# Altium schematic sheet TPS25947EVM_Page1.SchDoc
size 431 x 279 mm; Date: Not shown in title block; ApprovedBy: Not shown in title block; CheckedBy: Not shown in title block; Author: Not shown in title block; CompanyName: Not shown in title block; Engineer: Not shown in title block; Organization: Not shown in title block; Address1: Not shown in title block; Address2: Not shown in title block; Address3: Not shown in title block; Address4: Not shown in title block; DocumentNumber: 1; Revision: Use project parameter SCH_Rev; SheetNumber: 1; SheetTotal: 3; PageSetup: Record=PageOptions¦CenterHorizontal=True¦CenterVertical=True¦PrintScale=1.00¦XCorrection=1.00¦YCorrection=1.00¦PrintKind=0¦BorderSize=5000000¦LeftOffset=0¦BottomOffset=0¦Orientation=2¦PaperLength=1000¦PaperWidth=1000¦Scale=100¦PaperSource=15¦PrintQuality=600¦MediaType=1¦DitherType=10¦PaperKind=Letter¦PrintScaleMode=1
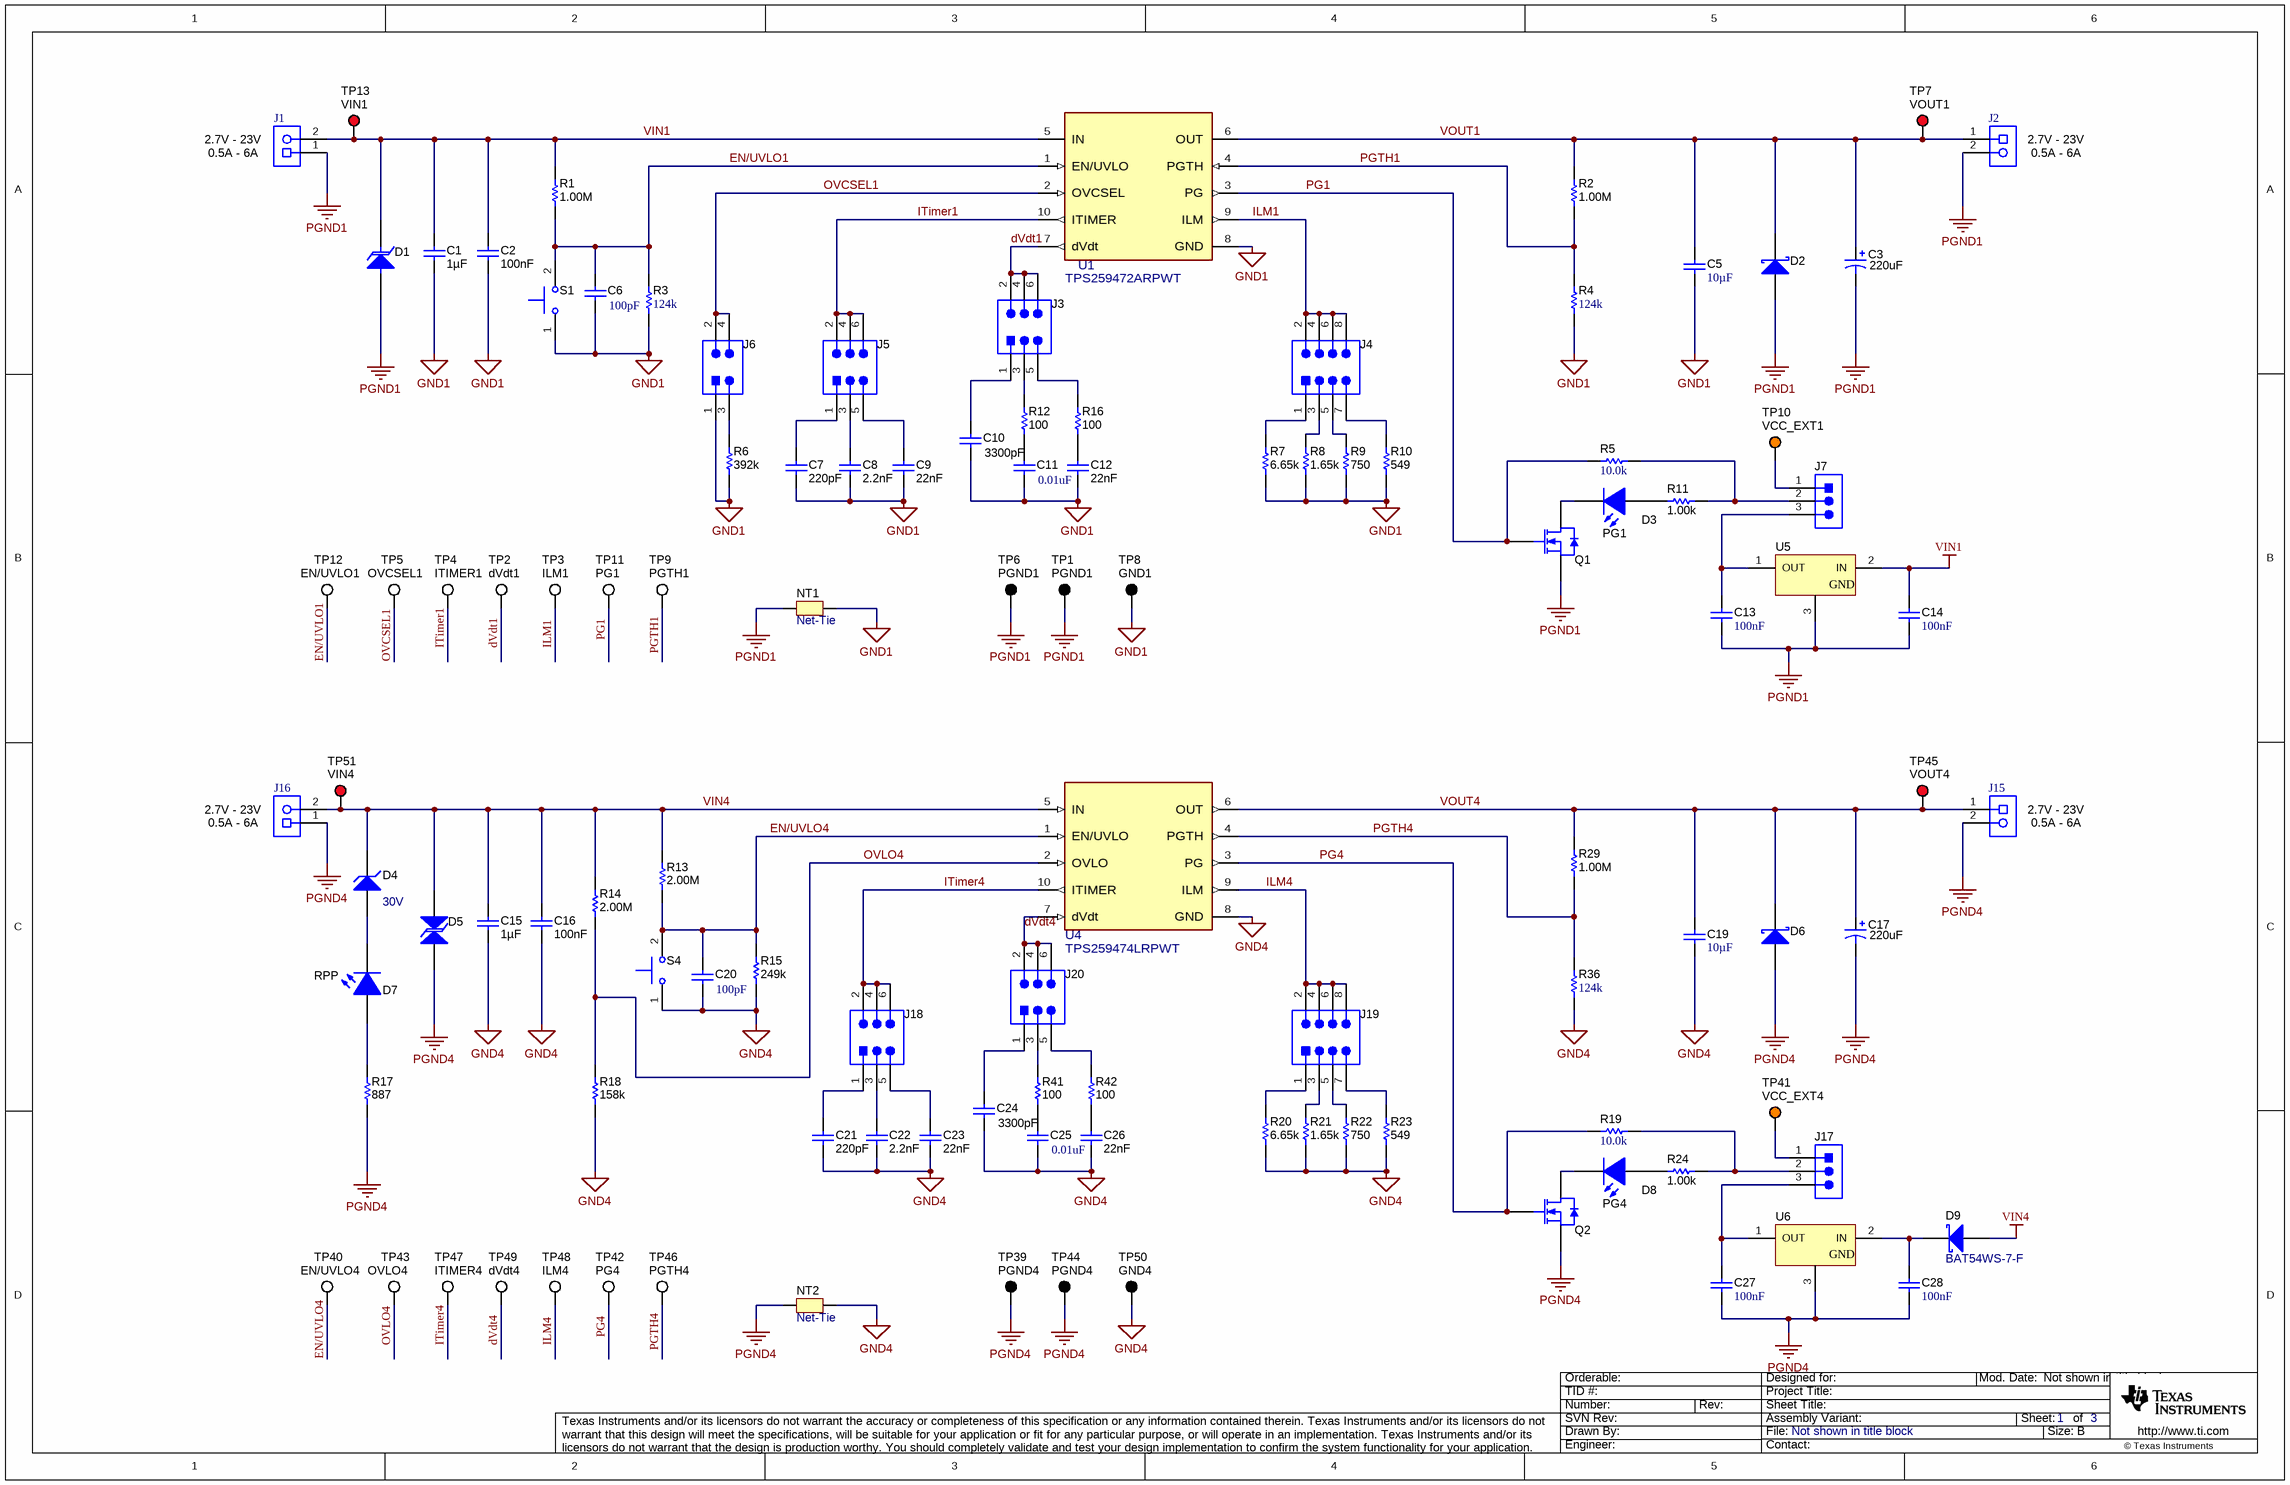
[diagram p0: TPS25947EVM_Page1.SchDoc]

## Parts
C1  Cap_F: 1µF  [0603]  (hidden comment: C1608X7R1V105K080AC)
C2  Cap_F: 100nF  [0603]  (hidden comment: C1608X7R1H104K080AA)
C3  ValueDisplayed: 220uF  [SM_RADIAL_G]  (hidden comment: EEE-FC1V221P)
C5  ValueDisplayed: 10µF  [1206_190]  (hidden comment: CGA5L1X7R1H106K160AC)
C6  ValueDisplayed: 100pF  [0603]  (hidden comment: 885012006057)
C7  Cap_F: 220pF  [0603]  (hidden comment: C0603C221K5RACTU)
C8  Cap_F: 2.2nF  [0603]  (hidden comment: C0603C222K5RAC)
C9  Cap_F: 22nF  [0603]  (hidden comment: C0603X223K5RACTU)
C10  ValueDisplayed: 3300pF  [0603]  (hidden comment: C0603X332K5RACTU)
C11  ValueDisplayed: 0.01uF  [0603]  (hidden comment: GRM1885C1H103JA01D)
C12  Cap_F: 22nF  [0603]  (hidden comment: C0603X223K5RACTU)
C13  Cap_F: 100nF  [0603]  (hidden comment: 06035C104KAT2A)
C14  Cap_F: 100nF  [0603]  (hidden comment: 06035C104KAT2A)
C15  Cap_F: 1µF  [0603]  (hidden comment: C1608X7R1V105K080AC)
C16  Cap_F: 100nF  [0603]  (hidden comment: C1608X7R1H104K080AA)
C17  ValueDisplayed: 220uF  [SM_RADIAL_G]  (hidden comment: EEE-FC1V221P)
C19  ValueDisplayed: 10µF  [1206_190]  (hidden comment: CGA5L1X7R1H106K160AC)
C20  ValueDisplayed: 100pF  [0603]  (hidden comment: 885012006057)
C21  Cap_F: 220pF  [0603]  (hidden comment: C0603C221K5RACTU)
C22  Cap_F: 2.2nF  [0603]  (hidden comment: C0603C222K5RAC)
C23  Cap_F: 22nF  [0603]  (hidden comment: C0603X223K5RACTU)
C24  ValueDisplayed: 3300pF  [0603]  (hidden comment: C0603X332K5RACTU)
C25  ValueDisplayed: 0.01uF  [0603]  (hidden comment: GRM1885C1H103JA01D)
C26  Cap_F: 22nF  [0603]  (hidden comment: C0603X223K5RACTU)
C27  Cap_F: 100nF  [0603]  (hidden comment: 06035C104KAT2A)
C28  Cap_F: 100nF  [0603]  (hidden comment: 06035C104KAT2A)
D1  SMBJ16A-13-F  [SMB]  (value not drawn)
D2  B330A-13-F  [SMA]  (value not drawn)
D3  value PG1  [LTST-C170KGKT_Green]  (hidden comment: LTST-C170KGKT)
D4  value 30V  [SOD-123]  (hidden comment: DDZ30D-7)
D5  SMBJ16CA  [SMB-Bi]  (value not drawn)
D6  B330A-13-F  [SMA]  (value not drawn)
D7  value RPP  [LED_LTST-C170_Red]  (hidden comment: LTST-C170KRKT)
D8  value PG4  [LTST-C170KGKT_Green]  (hidden comment: LTST-C170KGKT)
D9  BAT54WS-7-F  [SOD-323]
J1  282841-2  [TEC_282841-2]  (value not drawn)
J2  282841-2  [TEC_282841-2]  (value not drawn)
J3  PEC03DAAN  [SULLINS_PEC03DAAN]  (value not drawn)
J4  PEC04DAAN  [CONN_PEC04DAAN]  (value not drawn)
J5  PEC03DAAN  [SULLINS_PEC03DAAN]  (value not drawn)
J6  PEC02DAAN  [Sullins_PEC02DAAN]  (value not drawn)
J7  Header_3x1_Launchpad  [CONN_PEC03SAAN]  (value not drawn)
J15  282841-2  [TEC_282841-2]  (value not drawn)
J16  282841-2  [TEC_282841-2]  (value not drawn)
J17  Header_3x1_Launchpad  [CONN_PEC03SAAN]  (value not drawn)
J18  PEC03DAAN  [SULLINS_PEC03DAAN]  (value not drawn)
J19  PEC04DAAN  [CONN_PEC04DAAN]  (value not drawn)
J20  PEC03DAAN  [SULLINS_PEC03DAAN]  (value not drawn)
NT1  Net-Tie  [Net-Tie_0805_HV_NoOverlay]  (net tie, no BOM)
NT2  Net-Tie  [Net-Tie_0805_HV_NoOverlay]  (net tie, no BOM)
Q1  2N7002  [SOT-23]  (value not drawn)
Q2  2N7002  [SOT-23]  (value not drawn)
R1  ValueDisplayed: 1.00M  [0603]  (hidden comment: RC0603FR-071ML)
R2  ValueDisplayed: 1.00M  [0603]  (hidden comment: RC0603FR-071ML)
R3  ValueDisplayed: 124k  [0603]  (hidden comment: CRCW0603124KFKEA)
R4  ValueDisplayed: 124k  [0603]  (hidden comment: CRCW0603124KFKEA)
R5  ValueDisplayed: 10.0k  [0603]  (hidden comment: RG1608P-103-B-T5)
R6  ValueDisplayed: 392k  [0603]  (hidden comment: RC0603FR-07392KL)
R7  ValueDisplayed: 6.65k  [0603]  (hidden comment: RC0603FR-076K65L)
R8  ValueDisplayed: 1.65k  [0603]  (hidden comment: RC0603FR-071K65L)
R9  ValueDisplayed: 750  [0603]  (hidden comment: RC0603FR-07750RL)
R10  ValueDisplayed: 549  [0603]  (hidden comment: RC0603FR-07549RL)
R11  ValueDisplayed: 1.00k  [0603]  (hidden comment: RC0603FR-071KL)
R12  ValueDisplayed: 100  [0603]  (hidden comment: RC0603FR-07100RL)
R13  ValueDisplayed: 2.00M  [0603]  (hidden comment: RC0603FR-072ML)
R14  ValueDisplayed: 2.00M  [0603]  (hidden comment: RC0603FR-072ML)
R15  ValueDisplayed: 249k  [0603]  (hidden comment: RC0603FR-07249KL)
R16  ValueDisplayed: 100  [0603]  (hidden comment: RC0603FR-07100RL)
R17  ValueDisplayed: 887  [0603]  (hidden comment: RC0603FR-07887RL)
R18  ValueDisplayed: 158k  [0603]  (hidden comment: RC0603FR-07158KL)
R19  ValueDisplayed: 10.0k  [0603]  (hidden comment: RG1608P-103-B-T5)
R20  ValueDisplayed: 6.65k  [0603]  (hidden comment: RC0603FR-076K65L)
R21  ValueDisplayed: 1.65k  [0603]  (hidden comment: RC0603FR-071K65L)
R22  ValueDisplayed: 750  [0603]  (hidden comment: RC0603FR-07750RL)
R23  ValueDisplayed: 549  [0603]  (hidden comment: RC0603FR-07549RL)
R24  ValueDisplayed: 1.00k  [0603]  (hidden comment: RC0603FR-071KL)
R29  ValueDisplayed: 1.00M  [0603]  (hidden comment: RC0603FR-071ML)
R36  ValueDisplayed: 124k  [0603]  (hidden comment: CRCW0603124KFKEA)
R41  ValueDisplayed: 100  [0603]  (hidden comment: RC0603FR-07100RL)
R42  ValueDisplayed: 100  [0603]  (hidden comment: RC0603FR-07100RL)
S1  B3U-1000P  [SW_B3U-1000P]  (value not drawn)
S4  B3U-1000P  [SW_B3U-1000P]  (value not drawn)
TP1  PGND1  [Keystone5011]
TP2  dVdt1  [Keystone5012]
TP3  ILM1  [Keystone5012]
TP4  ITIMER1  [Keystone5012]
TP5  OVCSEL1  [Keystone5012]
TP6  PGND1  [Keystone5011]
TP7  VOUT1  [Keystone5010]
TP8  GND1  [Keystone5011]
TP9  PGTH1  [Keystone5012]
TP10  VCC_EXT1  [Keystone5013]
TP11  PG1  [Keystone5012]
TP12  EN/UVLO1  [Keystone5012]
TP13  VIN1  [Keystone5010]
TP39  PGND4  [Keystone5011]
TP40  EN/UVLO4  [Keystone5012]
TP41  VCC_EXT4  [Keystone5013]
TP42  PG4  [Keystone5012]
TP43  OVLO4  [Keystone5012]
TP44  PGND4  [Keystone5011]
TP45  VOUT4  [Keystone5010]
TP46  PGTH4  [Keystone5012]
TP47  ITIMER4  [Keystone5012]
TP48  ILM4  [Keystone5012]
TP49  dVdt4  [Keystone5012]
TP50  GND4  [Keystone5011]
TP51  VIN4  [Keystone5010]
U1  TPS259472ARPWT  [RPW0010A-MFG]
U4  TPS259474LRPWT  [RPW0010A-MFG]
U5  LM3480IM3-3.3/NOPB  [DBZ0003A_N]  (value not drawn)
U6  LM3480IM3-3.3/NOPB  [DBZ0003A_N]  (value not drawn)

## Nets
GND1: C1.2 C2.2 C5.2 C6.2 C7.2 C8.2 C9.2 C10.2 C11.2 C12.2 J6.1 NT1.2 R3.1 R4.1 R6.1 R7.1 R8.1 R9.1 R10.1 S1.1 TP8.1 U1.8(GND)
GND4: C15.2 C16.2 C19.2 C20.2 C21.2 C22.2 C23.2 C24.2 C25.2 C26.2 NT2.2 R15.1 R18.1 R20.1 R21.1 R22.1 R23.1 R36.1 S4.1 TP50.1 U4.8(GND)
PGND1: C3.2(-) C13.2 C14.2 D1.2(A) D2.2(A) J1.1 J2.2 NT1.1 Q1.2(S) TP1.1 TP6.1 U5.3(GND)
PGND4: C17.2(-) C27.2 C28.2 D5.1 D6.2(A) J15.2 J16.1 NT2.1 Q2.2(S) R17.1 TP39.1 TP44.1 U6.3(GND)
VIN1: C1.1 C2.1 C14.1 D1.1(K) J1.2 R1.2 TP13.1 U1.5(IN) U5.2(IN)
VIN4: C15.1 C16.1 D4.1(K) D5.2 D9.2(A) J16.2 R13.2 R14.2 TP51.1 U4.5(IN)
dVdt1: J3.2 J3.4 J3.6 TP2.1 U1.7(dVdt)
dVdt4: J20.2 J20.4 J20.6 TP49.1 U4.7(dVdt)
EN/UVLO1: C6.1 R1.1 R3.2 S1.2 TP12.1 U1.1(EN/UVLO)
EN/UVLO4: C20.1 R13.1 R15.2 S4.2 TP40.1 U4.1(EN/UVLO)
ILM1: J4.2 J4.4 J4.6 J4.8 TP3.1 U1.9(ILM)
ILM4: J19.2 J19.4 J19.6 J19.8 TP48.1 U4.9(ILM)
ITimer1: J5.2 J5.4 J5.6 TP4.1 U1.10(ITIMER)
ITimer4: J18.2 J18.4 J18.6 TP47.1 U4.10(ITIMER)
OVCSEL1: J6.2 J6.4 TP5.1 U1.2(OVCSEL)
OVLO4: R14.1 R18.2 TP43.1 U4.2(OVLO)
PG1: Q1.1(G) R5.1 TP11.1 U1.3(PG)
PG4: Q2.1(G) R19.1 TP42.1 U4.3(PG)
PGTH1: R2.1 R4.2 TP9.1 U1.4(PGTH)
PGTH4: R29.1 R36.2 TP46.1 U4.4(PGTH)
VOUT1: C3.1(+) C5.1 D2.1(K) J2.1 R2.2 TP7.1 U1.6(OUT)
VOUT4: C17.1(+) C19.1 D6.1(K) J15.1 R29.2 TP45.1 U4.6(OUT)
NetC7_1: C7.1 J5.1
NetC8_1: C8.1 J5.3
NetC9_1: C9.1 J5.5
NetC10_1: C10.1 J3.1
NetC11_1: C11.1 R12.1
NetC12_1: C12.1 R16.1
NetC13_1: C13.1 J7.3 U5.1(OUT)
NetC21_1: C21.1 J18.1
NetC22_1: C22.1 J18.3
NetC23_1: C23.1 J18.5
NetC24_1: C24.1 J20.1
NetC25_1: C25.1 R41.1
NetC26_1: C26.1 R42.1
NetC27_1: C27.1 J17.3 U6.1(OUT)
NetC28_1: C28.1 D9.1(K) U6.2(IN)
NetD3_1: D3.1(A) R11.1
NetD3_2: D3.2(K) Q1.3(D)
NetD4_2: D4.2(A) D7.2(K)
NetD7_1: D7.1(A) R17.2
NetD8_1: D8.1(A) R24.1
NetD8_2: D8.2(K) Q2.3(D)
NetJ3_3: J3.3 R12.2
NetJ3_5: J3.5 R16.2
NetJ4_1: J4.1 R7.2
NetJ4_3: J4.3 R8.2
NetJ4_5: J4.5 R9.2
NetJ4_7: J4.7 R10.2
NetJ6_3: J6.3 R6.2
NetJ7_1: J7.1 TP10.1
NetJ7_2: J7.2 R5.2 R11.2
NetJ17_1: J17.1 TP41.1
NetJ17_2: J17.2 R19.2 R24.2
NetJ19_1: J19.1 R20.2
NetJ19_3: J19.3 R21.2
NetJ19_5: J19.5 R22.2
NetJ19_7: J19.7 R23.2
NetJ20_3: J20.3 R41.2
NetJ20_5: J20.5 R42.2

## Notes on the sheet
- (near J1) 2.7V - 23V
- (near J1) 0.5A - 6A
- (near J2) 2.7V - 23V
- (near J2) 0.5A - 6A
- (near J16) 2.7V - 23V
- (near J16) 0.5A - 6A
- (near J15) 2.7V - 23V
- (near J15) 0.5A - 6A

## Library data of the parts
C1 C15 = CMP-0007052-4: CAP, CERM, 1 uF, 35 V, +/- 10%, X7R, 0603; Manufacturer: TDK; TaMin_C: -55°C; Polarized: N; SizeAreaWB_mm2: 4.68; Value1: Unknown; U/M: EA; Value: 1uF; TaMax_C: 125°C; SizeZ_mm: 1; SizeX_mm: 1.6; SizeY_mm: 0.8; Value2: 35V; SizeArea_mm2: 1.28; AEC Category: Q200
C2 C16 = CMP-0007044-1: CAP, CERM, 0.1 uF, 50 V, +/- 10%, X7R, 0603; Manufacturer: TDK; TaMin_C: -55°C; ESR_ohm: 0.0296; Polarized: N; SizeAreaWB_mm2: 4.68; Value1: 0.0296 ohm; U/M: EA; Value: 0.1uF; TaMax_C: 125°C; SizeZ_mm: 1; SizeX_mm: 1.6; SizeY_mm: 0.8; Value2: 50V; SizeArea_mm2: 1.28; IRMS_A: 971.99mA; AEC Category: Q200
C3 C17 = CMP-0010667-1: CAP, AL, 220 uF, 35 V, +/- 20%, 0.15 ohm, SMD; Manufacturer: Panasonic; TaMin_C: -40°C; ESR_ohm: 1.5d; Polarized: Y; SizeAreaWB_mm2: 172.2; U/M: EA; Value: 220uF; TaMax_C: 105°C; SizeZ_mm: 10.2; SizeX_mm: 12; SizeY_mm: 10.3; Cap_Case: G; Value2: 35V; SizeArea_mm2: 123.6; CompType: Capacitor; Cap_F: 220µF; IRMS_A: 6.7dA; AEC Category: Q200
C5 C19 = CMP-0085950-1: CAP, CERM, 10 µF, 50 V,+/- 10%, X7R, AEC-Q200 Grade 1, 1206; Manufacturer: TDK; SizeZ_mm: 1.9; Value: 10uF; Value2: 50V; Cap_Case: 1206; AEC Grade: 1; TaMin_C: -55°C; U/M: EA; SizeArea_mm2: 5.12; TaMax_C: 125°C; AEC Qualified: Y; AEC Category: Q200; SizeX_mm: 3.2; SizeY_mm: 1.6; Polarized: N; SizeAreaWB_mm2: 10.92
C6 C20 = CMP-0006822-4: CAP, CERM, 100 pF, 50 V, +/- 5%, C0G/NP0, 0603; Manufacturer: Wurth Elektronik; TaMin_C: -55°C; Polarized: N; SizeAreaWB_mm2: 4.68; Value1: Unknown; U/M: EA; Value: 100pF; TaMax_C: 125°C; SizeZ_mm: 1; SizeX_mm: 1.6; SizeY_mm: 0.8; Value2: 50V; SizeArea_mm2: 1.28; CompType: Capacitor; AEC Category: Q200
C7 C21 = CMP-0006895-2: CAP, CERM, 220 pF, 50 V, +/- 10%, X7R, 0603; Manufacturer: Kemet; TaMin_C: -55°C; Polarized: N; SizeAreaWB_mm2: 4.68; Value1: Unknown; U/M: EA; Value: 220pF; TaMax_C: 125°C; SizeZ_mm: 1; SizeX_mm: 1.6; SizeY_mm: 0.8; Value2: 50V; SizeArea_mm2: 1.28; AEC Category: Q200
C8 C22 = CMP-0006897-4: CAP, CERM, 2200 pF, 50 V, +/- 10%, X7R, 0603; Manufacturer: Kemet; TaMin_C: -55°C; Polarized: N; SizeAreaWB_mm2: 4.68; Value1: Unknown; U/M: EA; Value: 2200pF; TaMax_C: 125°C; SizeZ_mm: 1; SizeX_mm: 1.6; SizeY_mm: 0.8; Value2: 50V; SizeArea_mm2: 1.28; AEC Category: Q200
C9 C12 C23 C26 = CMP-0006984-4: CAP, CERM, 0.022 uF, 50 V, +/- 10%, X7R, 0603; Manufacturer: Kemet; TaMin_C: -55°C; Polarized: N; SizeAreaWB_mm2: 4.68; Value1: Unknown; U/M: EA; TaMax_C: 125°C; SizeZ_mm: 1; SizeX_mm: 1.6; SizeY_mm: 0.8; Value2: 50V; SizeArea_mm2: 1.28; AEC Category: Q200
C10 C24 = CMP-0006985-4: CAP, CERM, 3300 pF, 50 V, +/- 10%, X7R, 0603; Manufacturer: Kemet; TaMin_C: -55°C; Polarized: N; SizeAreaWB_mm2: 4.68; Value1: Unknown; U/M: EA; Value: 3300pF; TaMax_C: 125°C; SizeZ_mm: 1; SizeX_mm: 1.6; SizeY_mm: 0.8; Value2: 50V; SizeArea_mm2: 1.28; CompType: Capacitor; Cap_F: 3.3nF; AEC Category: Q200
C11 C25 = CMP-0007174-4: CAP, CERM, 0.01 uF, 50 V, +/- 5%, C0G/NP0, 0603; Manufacturer: MuRata; TaMin_C: -55°C; Polarized: N; SizeAreaWB_mm2: 4.68; Value1: Unknown; U/M: EA; Value: 0.01uF; TaMax_C: 125°C; SizeZ_mm: 1; SizeX_mm: 1.6; SizeY_mm: 0.8; Value2: 50V; SizeArea_mm2: 1.28; Cap_F: 10nF; AEC Category: Q200
C13 C14 C27 C28 = CMP-0006802-4: CAP, CERM, 0.1 uF, 50 V, +/- 10%, X7R, 0603; Manufacturer: AVX; TaMin_C: -55°C; Polarized: N; SizeAreaWB_mm2: 4.68; Value1: Unknown; U/M: EA; Value: 0.1uF; TaMax_C: 125°C; SizeZ_mm: 1; SizeX_mm: 1.6; SizeY_mm: 0.8; Value2: 50V; SizeArea_mm2: 1.28; AEC Category: Q200
D1 = CMP-0005547-4: Diode, TVS, Uni, 16 V, 26 Vc, SMB; Manufacturer: Diodes Inc.; Value: 16V; SizeArea_mm2: 21.336; SizeY_mm: 3.81; Vbr_Min: 17.8V; Ppk: 600W; AEC Category: Q101; SizeZ_mm: 2.6; Ipp: 23.1A; SizeAreaWB_mm2: 44.156; Vc: 26V; Vbr_Max: 20.5V; SizeX_mm: 5.6
D2 D6 = CMP-0028350-2: Diode, Schottky, 30 V, 3 A, SMA; Manufacturer: Diodes Inc.; Io_A: 3A; SizeZ_mm: 2.87; SizeAreaWB_mm2: 37.3428; Value: 30V; TJmax_C: 125°C; Green_Lifecycle: Active; SizeY_mm: 2.92; Vf_V: 5dV; Green_REACh: Passed; SizeArea_mm2: 16.3228; AEC Category: Q101; Value2: 0.5V; SizeX_mm: 5.59; RJC_CperW: 25
D3 D8 = CMP-0002888-1: LED, Green, SMD; Manufacturer: Lite-On; Type: AlInGaP; Vf_V: 2V; Io_A: 20mA; Value1: W; U/M: EA
D4 = CMP-0085162-1: Diode, Zener, 30 V, 500 mW, SOD-123; Manufacturer: Diodes Inc.; SizeZ_mm: 1.35; AEC Qualified: N; SizeAreaWB_mm2: 13.095; SizeY_mm: 1.7; Value1: 0.5W; RJA_CperW: 425; SizeArea_mm2: 6.545; AEC Category: Q101; SizeX_mm: 3.85; Power_W: 500mW
D5 = CMP-0005548-3: Diode, TVS, Bi, 16 V, SMB; Manufacturer: Littelfuse; Value: 16V; SizeAreaWB_mm2: 44.156; RJA_CperW: 100; AEC Category: Q101; Value1: 600W; SizeX_mm: 5.6; SizeZ_mm: 2.6; SizeY_mm: 3.81; SizeArea_mm2: 21.336
D7 = CMP-0002829-2: LED, Red, SMD; Manufacturer: Lite-On; Type: AlInGaP; Vf_V: 2V; Io_A: 20mA; Value1: W; U/M: EA; SizeAreaWB_mm2: 6.75; SizeArea_mm2: 2.5; SizeX_mm: 2; SizeY_mm: 1.25; SizeZ_mm: 1.2
D9 = CMP-0028458-1: Diode, Schottky, 30 V, 0.2 A, SOD-323; Manufacturer: Diodes Inc.; Io_A: 200mA; Green_Lifecycle: Active; SizeAreaWB_mm2: 8.695; Vr_V: 30V; Green_REACh: Passed; Value1: 0.2A; TJmax_C: 125°C; U/M: EA; Value: 30V; SizeZ_mm: 1; SizeX_mm: 2.7; SizeY_mm: 1.35; Vf_V: 700mV; Value2: 0.7V; SizeArea_mm2: 3.645; AEC Category: Q101
J1 J2 J15 J16 = CMP-0054973-1: Terminal Block, 2x1, 5.08mm, TH; Manufacturer: TE Connectivity; CNHeader: FALSE; Green_Lifecycle: Active; Green_REACh: Passed; CT: TRUE
J3 J5 J18 J20 = CMP-0054552-1: Header, 100mil, 3x2, Tin, TH; Manufacturer: Sullins Connector Solutions; CNHeader: TRUE; Current_A: 3A; Green_Lifecycle: Not Set; Shrouded: N; Gender: Male; Green_REACh: Incomplete; Voltage_V: 1.8kV; Row_Count: 2; RowSpacing_mm: 2.54; CT: FALSE; Cert_UL: Y
J4 J19 = CMP-0054542-1: Header, 100mil, 4x2, Tin, TH; Manufacturer: Sullins Connector Solutions; CNHeader: TRUE; Current_A: 3A; Green_Lifecycle: Not Set; Shrouded: N; Gender: Male; Green_REACh: Incomplete; Voltage_V: 1.8kV; Row_Count: 2; RowSpacing_mm: 2.54; CT: FALSE; Cert_UL: Y
J6 = CMP-0054558-1: Header, 100mil, 2x2, Tin, TH; Manufacturer: Sullins Connector Solutions; CNHeader: TRUE; Green_Lifecycle: Not Set; Green_REACh: Incomplete; CT: FALSE
J7 J17 = CMP-0002338-1: Header, 100mil, 3x1, Tin, TH; PartNumber: PEC03SAAN; Manufacturer: Sullins Connector Solutions; Cert_UL: Y; CNHeader: TRUE; CT: FALSE; Current_A: 3A; Gender: Male; Green_Lifecycle: Not Set; Green_REACh: Incomplete; Pitch_mm: 2.54; Row_Count: 1; Shrouded: N; Voltage_V: 1.8kV
NT1 NT2 = CMP-0078142-2: Single point connection between nets.
Q1 Q2 = CMP-0000768-1: MOSFET, N-CH, 60 V, 115 A, SOT-23; Manufacturer: Fairchild Semiconductor; SizeZ_mm: 1.1; ChType: N; VdsMax_V: 60V; SizeX_mm: 2.5; SizeY_mm: 3; Vgs_V: 20V; Value: 60V; SizeArea_mm2: 7.5; AEC Category: Q101; IdsMax_A: 115A; SizeAreaWB_mm2: 14; U/M: EA
R1 R2 R29 = CMP-0022899-4: RES, 1.00 M, 1%, 0.1 W, 0603; Manufacturer: Yageo; Power_W: 100mW; TempCo: 100 ppm/C; Value_Code: 1M00; Value: 1.00Meg; EIA_Code: E96; Res_ohm: 1M; SizeX_mm: 1.6; SizeY_mm: 0.8; SizeZ_mm: 1; Value2: 0.1W; SizeArea_mm2: 1.28; AEC Qualified: N; VDC_V: 75V; AEC Category: Q200; SizeAreaWB_mm2: 4.68
R3 R4 R36 = CMP-0022026-4: RES, 124 k, 1%, 0.1 W, AEC-Q200 Grade 0, 0603; Manufacturer: Vishay-Dale; Power_W: 100mW; TempCo: 100 ppm/C; Value: 124k; EIA_Code: E96; SizeX_mm: 1.6; SizeY_mm: 0.8; SizeZ_mm: 1; Value2: 0.1W; SizeArea_mm2: 1.28; AEC Qualified: Y; VDC_V: 75V; AEC Category: Q200; AEC Grade: 0
R5 R19 = CMP-0023404-3: RES, 10.0 k, 0.1%, 0.1 W, 0603; Manufacturer: Susumu Co Ltd; Power_W: 100mW; TempCo: 25 ppm/C; Value_Code: 10k0; U/M: EA; Value: 10.0k; EIA_Code: E192; Res_ohm: 10k; SizeX_mm: 1.6; SizeY_mm: 0.8; SizeZ_mm: 1; Value2: 0.1W; SizeArea_mm2: 1.28; CompType: Resistor; VDC_V: 75V; AEC Category: Q200
R6 = CMP-0023070-4: RES, 392 k, 1%, 0.1 W, 0603; Manufacturer: Yageo; Power_W: 100mW; TempCo: 100 ppm/C; Value: 392k; EIA_Code: E96; SizeX_mm: 1.6; SizeY_mm: 0.8; SizeZ_mm: 1; Value2: 0.1W; SizeArea_mm2: 1.28; AEC Qualified: N; VDC_V: 75V; AEC Category: Q200; SizeAreaWB_mm2: 4.68
R7 R20 = CMP-0023251-5: RES, 6.65 k, 1%, 0.1 W, 0603; Manufacturer: Yageo; Power_W: 100mW; TempCo: 100 ppm/C; Value_Code: 6k65; Value: 6.65k; EIA_Code: E96; SizeX_mm: 1.6; SizeY_mm: 0.8; SizeZ_mm: 1; Value2: 0.1W; SizeArea_mm2: 1.28; AEC Qualified: N; VDC_V: 75V; AEC Category: Q200; SizeAreaWB_mm2: 4.68
R8 R21 = CMP-0022885-5: RES, 1.65 k, 1%, 0.1 W, 0603; Manufacturer: Yageo; Power_W: 100mW; TempCo: 100 ppm/C; Value_Code: 1k65; Value: 1.65k; EIA_Code: E96; SizeX_mm: 1.6; SizeY_mm: 0.8; SizeZ_mm: 1; Value2: 0.1W; SizeArea_mm2: 1.28; AEC Qualified: N; VDC_V: 75V; AEC Category: Q200; SizeAreaWB_mm2: 4.68
R9 R22 = CMP-0023266-5: RES, 750, 1%, 0.1 W, 0603; Manufacturer: Yageo; Power_W: 100mW; TempCo: 100 ppm/C; Value_Code: 750R; Value: 750; EIA_Code: E96; SizeX_mm: 1.6; SizeY_mm: 0.8; SizeZ_mm: 1; Value2: 0.1W; SizeArea_mm2: 1.28; AEC Qualified: N; VDC_V: 75V; AEC Category: Q200; SizeAreaWB_mm2: 4.68
R10 R23 = CMP-0023179-5: RES, 549, 1%, 0.1 W, 0603; Manufacturer: Yageo; Power_W: 100mW; TempCo: 100 ppm/C; Value_Code: 549R; Value: 549; EIA_Code: E96; SizeX_mm: 1.6; SizeY_mm: 0.8; SizeZ_mm: 1; Value2: 0.1W; SizeArea_mm2: 1.28; AEC Qualified: N; VDC_V: 75V; AEC Category: Q200; SizeAreaWB_mm2: 4.68
R11 R24 = CMP-0022895-5: RES, 1.00 k, 1%, 0.1 W, 0603; Manufacturer: Yageo; Power_W: 100mW; TempCo: 100 ppm/C; Value_Code: 1k00; Value: 1.00k; EIA_Code: E96; Res_ohm: 1k; SizeX_mm: 1.6; SizeY_mm: 0.8; SizeZ_mm: 1; Value2: 0.1W; SizeArea_mm2: 1.28; AEC Qualified: N; VDC_V: 75V; AEC Category: Q200; SizeAreaWB_mm2: 4.68
R12 R16 R41 R42 = CMP-0022736-4: RES, 100, 1%, 0.1 W, 0603; Manufacturer: Yageo; Power_W: 100mW; TempCo: 100 ppm/C; Value_Code: 100R; Value: 100; EIA_Code: E96; SizeX_mm: 1.6; SizeY_mm: 0.8; SizeZ_mm: 1; Value2: 0.1W; SizeArea_mm2: 1.28; AEC Qualified: N; VDC_V: 75V; AEC Category: Q200; SizeAreaWB_mm2: 4.68
R13 R14 = CMP-0023004-4: RES, 2.00 M, 1%, 0.1 W, 0603; Manufacturer: Yageo; Power_W: 100mW; TempCo: 100 ppm/C; Value_Code: 2M00; Value: 2.00Meg; EIA_Code: E96; Res_ohm: 2M; SizeX_mm: 1.6; SizeY_mm: 0.8; SizeZ_mm: 1; Value2: 0.1W; SizeArea_mm2: 1.28; AEC Qualified: N; VDC_V: 75V; AEC Category: Q200; SizeAreaWB_mm2: 4.68
R15 = CMP-0022941-4: RES, 249 k, 1%, 0.1 W, 0603; Manufacturer: Yageo; Power_W: 100mW; TempCo: 100 ppm/C; Value: 249k; EIA_Code: E96; SizeX_mm: 1.6; SizeY_mm: 0.8; SizeZ_mm: 1; Value2: 0.1W; SizeArea_mm2: 1.28; AEC Qualified: N; VDC_V: 75V; AEC Category: Q200; SizeAreaWB_mm2: 4.68
R17 = CMP-0023303-5: RES, 887, 1%, 0.1 W, 0603; Manufacturer: Yageo; Power_W: 100mW; TempCo: 100 ppm/C; Value_Code: 887R; Value: 887; EIA_Code: E96; SizeX_mm: 1.6; SizeY_mm: 0.8; SizeZ_mm: 1; Value2: 0.1W; SizeArea_mm2: 1.28; AEC Qualified: N; VDC_V: 75V; AEC Category: Q200; SizeAreaWB_mm2: 4.68
R18 = CMP-0022812-4: RES, 158 k, 1%, 0.1 W, 0603; Manufacturer: Yageo; Power_W: 100mW; TempCo: 100 ppm/C; Value: 158k; EIA_Code: E96; SizeX_mm: 1.6; SizeY_mm: 0.8; SizeZ_mm: 1; Value2: 0.1W; SizeArea_mm2: 1.28; AEC Qualified: N; VDC_V: 75V; AEC Category: Q200; SizeAreaWB_mm2: 4.68
S1 S4 = CMP-0002150-2: SWITCH TACTILE SPST-NO 0.05A 12V; Manufacturer: Omron Electronic Components; CurrentRating_mA: 50A; PositionCount: 1; SwitchFunction: Off-Mom
TP1 TP6 TP8 TP39 TP44 TP50 = CMP-0055148-1: Test Point, Multipurpose, Black, TH; Manufacturer: Keystone; PartNumber: 5011; CNHeader: FALSE; Green_Lifecycle: Active; Green_REACh: Passed; ContactFinish: Silver; CT: TRUE
TP2-TP5 TP9 TP11 TP12 TP40 TP42 TP43 TP46-TP49 = CMP-0055149-1: Test Point, Multipurpose, White, TH; Manufacturer: Keystone; PartNumber: 5012; CNHeader: FALSE; Green_Lifecycle: Active; Green_REACh: Passed; ContactFinish: Silver; CT: TRUE
TP7 TP13 TP45 TP51 = CMP-0055147-1: Test Point, Multipurpose, Red, TH; Manufacturer: Keystone; PartNumber: 5010; CNHeader: FALSE; Green_Lifecycle: Active; Green_REACh: Passed; ContactFinish: Silver; CT: TRUE
TP10 TP41 = CMP-0055150-1: Test Point, Multipurpose, Orange, TH; Manufacturer: Keystone; PartNumber: 5013; CNHeader: FALSE; Green_Lifecycle: Active; Green_REACh: Passed; ContactFinish: Silver; CT: TRUE
U1 = CMP-0090373-1: 2.7- 23V, 5.5 A, 28 mΩ Reverse Current Blocking eFuse with Input Reverse Polarity Protection; Manufacturer: Texas Instruments; Threshold Voltage: 1.2/1.1V; Reset Type: Active Low; AEC Qualified: No; Standoff Height: 0mm; Number Of Outputs: 1; SizeZ_mm: 1mm; Min Supply Voltage: 2.7V; Nominal Supply Current: 450uA; Reset Timeout: 100ms; TJmax_C: +125°C
U4 = CMP-0088329-1: 2.7- 23V, 5.5 A, 28 mΩ Reverse Current Blocking eFuse with Input Reverse Polarity Protection; Manufacturer: Texas Instruments; AEC Qualified: No; Nominal Supply Current: 0.5-6A; Threshold Voltage: 1.2/1.1V; Standoff Height: 0mm; Number Of Rails Monitored: 1; SizeZ_mm: 1mm; Min Supply Voltage: 2.7V; Reset Type: Active Low; TJmax_C: +125°C; Output Voltage: 42V
U5 U6 = CMP-0071020-1: 100 mA, Quasi Low-Dropout Linear Voltage Regulator, 3-pin SOT-23, Pb-Free; Manufacturer: Texas Instruments; PowerWise: N; CompType: LDO IC; PackageTopMarking: L0A*XTT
